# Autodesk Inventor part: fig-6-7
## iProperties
Shininess: 77.0
Angle Display Precision: 2
Document Length Units: 11269
Document Angle Units: 11279
Document Time Units: 11290
Document Mass Units: 11283
Document Length Units Precision: 3
Document Angle Units Precision: 2
Created: 2001-12
Part Number: fig-6-7
Document SubType Name: Modeling
Designer: Renu Muthoo
Density: 1 g/cm^3
Density: 0.0
Volumn: 0.0
Area: 0.0
PropertySet Name: Model Information
Control State: 0
Master: False
Checked Out: False
Author: Renu Muthoo
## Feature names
1. Extrusion1
2. Extrusion2
3. Fillet1
4. Hole3
5. Hole4
6. Hole5
7. Hole6
8. Fillet2
